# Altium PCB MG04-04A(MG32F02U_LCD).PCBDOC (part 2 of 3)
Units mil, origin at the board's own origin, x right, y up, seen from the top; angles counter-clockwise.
Board outline 5905.51 x 3543.31 mil, 2 copper layers (Top Layer, Bottom Layer); 293 components, 227 nets, 959 pads, 508 vias.
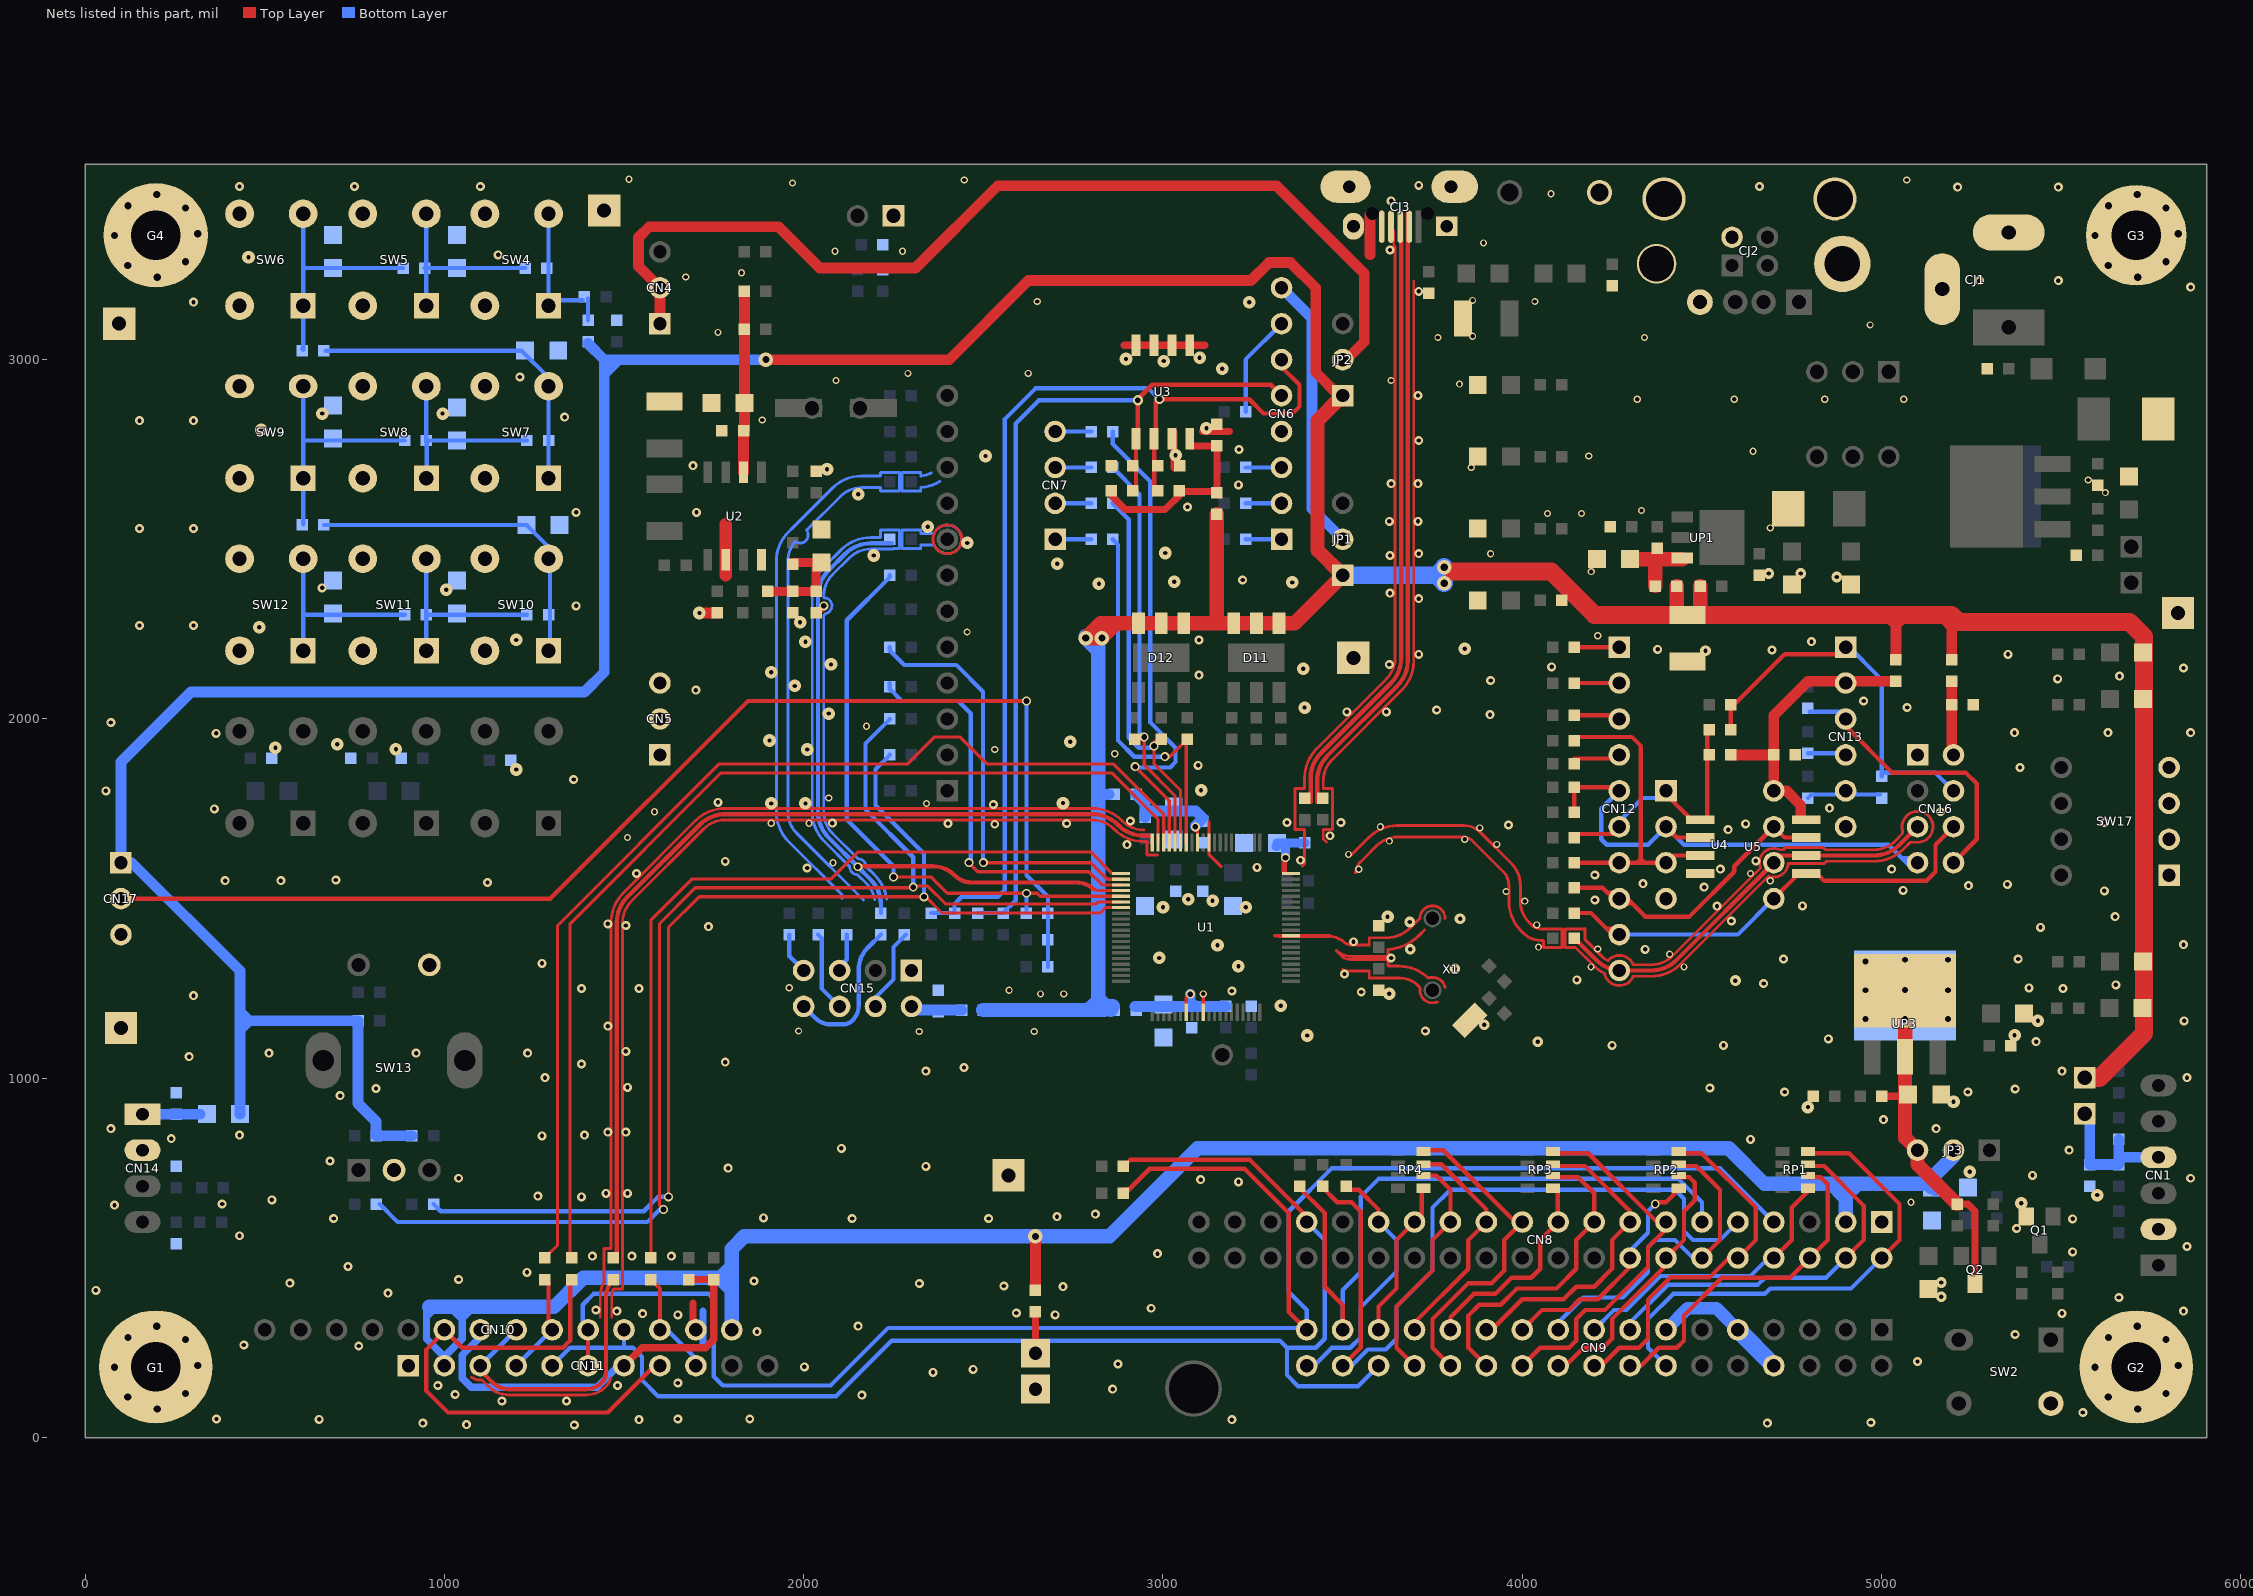
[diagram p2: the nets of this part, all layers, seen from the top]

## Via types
v1: diameter 25, hole 12, Top Layer to Bottom Layer, tented both sides, 253 vias
v2: diameter 25, hole 16, Top Layer to Bottom Layer, tented both sides, 83 vias
v3: diameter 20, hole 12, Top Layer to Bottom Layer, tented both sides, 77 vias
v4: diameter 35, hole 12, Top Layer to Bottom Layer, tented both sides, 64 vias
v5: diameter 40, hole 20, Top Layer to Bottom Layer, tented both sides, 16 vias
v6: diameter 30, hole 12, Top Layer to Bottom Layer, tented both sides, 13 vias
v7: diameter 28, hole 16, Top Layer to Bottom Layer, tented both sides, 2 vias

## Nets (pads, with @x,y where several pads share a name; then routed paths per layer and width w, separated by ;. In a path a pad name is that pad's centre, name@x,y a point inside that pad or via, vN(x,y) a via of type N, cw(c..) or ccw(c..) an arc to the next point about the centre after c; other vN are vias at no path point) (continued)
+LCD_LDO: C10.1 FB10.1 JP3.3 Q2.3 R9.1 UP3.2 UP3.4 | length 1102.5
  Top Layer w20: R9.1@5010,950 C10.1@5065,950 ; FB10.1@5210,650 5240,650 5260,630 Q2.3@5260,427.26
  Top Layer w32: UP3.4@5065,1175 UP3.4@5065,1176 ; UP3.4@5066,1150 5066,1165 UP3.4@5066,1175
  Top Layer w40: 5065,910 5065,835 ; UP3.2@5065,1082 UP3.2@5065,1060 C10.1@5065,950 ; UP3.4@5065,1266 5066,1265 5066,1165 UP3.2@5066,1082 ; C10.1@5074,950 C10.1@5065,950 ; FB10.1@5210,650 5100,760 JP3.3@5100,800 5065,835 ; 5065,835 C10.1@5065,950
  other v2: 4955,1165 5065,1165 5185,1165 4955,1245 5185,1245 5065,1246 4955,1325 5065,1330 5185,1330
+LCD_VCC: C36.1 CN8.2 CN10.1 CN11.2 JP3.2 R64.2 | length 5607.7
  Top Layer w30: R64.2@2645,410 v5(2645,560)
  Bottom Layer w20: 950,363 950,275 CN11.2@1000,225 ; 951,336.81 976,361.81 ; CN11.2@1000,200 CN11.2@1000,225 ; 1023,355 1048,330 ; 1050,350 1050,332 ; 1075,357 1050,332 ; 1761,436 1786,411 ; 1762,452 1787,477 ; CN11.2@1000,225 1050,275 1050,332
  Bottom Layer w30: 4860,700 4890,670 ; 4900,666 4940,706 ; C36.1@5150,686 C36.1@5150,706
  Bottom Layer w40: 958,363.69 1305,363.69 1386.31,445 1800,445 ; CN10.1@1800,300 1800,445 ; CN8.2@4900,600 4900,666 4900,706 ; C36.1@5140,696 C36.1@5140,706 ; JP3.2@5200,800 5200,783 5140,723 C36.1@5140,706 ; 1800,445 1800,525 1835,560 v5(2645,560) 2851,560 3096,805 4575,805 4674,706 4900,706 ; 4900,706 4940,706 C36.1@5140,706
+V33_MG: C21.1 R17.1 U1.60 | length 144.8
  Top Layer w15: 3338,1575 v2@3338,1613.77
  Bottom Layer w25: C21.1@3315,1645 C21.1@3317.81,1645 ; C21.1@3317.81,1655 R17.1@3395,1655 ; v2(3341,1614) C21.1@3341,1640
+VDD: CN17.1 D7.1 D8.1 D9.1 D10.1 D11.1 D11.3 D11.5 D12.1 D12.3 D12.5 D13.1 FB2.2 FB3.2 FB4.1 FB5.2 FB6.2 FB8.1 FB11.2 FB12.2 FB13.2 JP1.1 JP2.1 R3.1 R105.1 R115.1 R116.2 R118.2 TC3.1 | length 15368.9
  Top Layer w20: 5013,2282 5040,2255 5067,2282 ; 5168,2277 5195,2250 5215,2270 5222,2277
  Top Layer w30: v5(1895,3000) 2405,3000 2625,3220 3245,3220 3295,3270 3355,3270 3425,3200 3425,2965 3495,2895 JP2.1@3500,2890 ; JP1.1@3500,2400 JP1.1@3510,2400 ; FB11.2@5040,2165 5040,2255 5040,2270 ; FB13.2@5195,2180 5195,2250 5195,2290
  Top Layer w40: v5(2830,2225) v5@2828.54,2225 ; 3150,2268.46 FB8.1@3150,2570 ; JP2.1@3495,2895 3430,2830 3430,2470 JP1.1@3500,2400 3366.46,2266.46 D11.1@3322.99,2266.46 D11.3@3260,2266.46 D11.5@3197.01,2266.46 D12.1@3057.99,2266.46 D12.3@2995,2266.46 D12.5@2932.01,2266.46 2870,2266.46 ; JP2.1@3500,2890 JP2.1@3500,2900 ; TC3.1@4430,2300 FB3.2@4430,2370 ; TC3.1@4495,2300 FB2.2@4495,2370 ; v5@2828.54,2225 2870,2266.46 ; v5@2828.54,2225 v5(2785,2225) 2826.46,2266.46 2870,2266.46
  Top Layer w50: 3810,2410 4080.59,2410 4200.59,2290 TC3.1@4460,2290 ; TC3.1@4506,2290 5195,2290 5215,2270 5690,2270 5730,2230 5730,1125 ; FB6.2@5565,1001 5606,1001 5730,1125 ; D9.1@5730,2055 5730,1125
  Bottom Layer w12: 2778,1195 2808,1225 ; 2830,1232 FB5.2@2860,1202
  Bottom Layer w30: D13.1@431,900 431,1135 ; R118.2@910,840 R116.2@810,840 810,880 760,930 R115.1@760,1160 456,1160 ; R105.1@1400,3045 1445,3000 ; v5@1900,3000 v5(1895,3000) 1485,3000 ; 2820,1790 FB4.1@2850,1790 ; JP1.1@3490,2405 3505,2405 JP1.1@3510,2400 ; 431,1135 431,1160 ; 431,1135 456,1160 ; 431,1160 456,1160 ; 431,1160 431,1185 ; 431,1185 431,1299 130,1600 CN17.1@100,1600 100,1880 295,2075 1390,2075 1445,2130 1445,2960 ; 431,1185 456,1160 ; 1445,2960 1485,3000 ; 1445,2960 1445,3000 ; 1445,3000 1485,3000
  Bottom Layer w40: FB12.2@2500,1190 2837,1190 ; v5(2785,2225) 2820,2190 ; v5@2785,2230 v5@2830,2230 ; v5@2820,2220.86 2820,2190 ; FB5.2@2855,1190 FB5.2@2855,1200 ; FB5.2@2860,1200 FB5.2@2855,1200 ; v5@3787.7,2377.7 v5@3787.7,2422.3 ; 2820,2190 2820,1790 2820,1200 FB5.2@2855,1200
  Bottom Layer w50: JP1.1@3510,2400 3760.4,2400 ; 3780,2400 3760.4,2400 ; v5(3782.7,2377.7) 3760.4,2400 ; v5(3782.7,2422.3) 3760.4,2400
+VDD_AMP: C26.1 C27.1 FB7.2 FB14.2 U2.6 | length 498.3
  Top Layer w30: U2.6@1832.71,2686.65 C27.1@1832.71,2802.71 C27.1@1832.71,2805 ; C27.1@1835,2805 FB7.2@1835,3085 FB14.2@1835,3185
+VDD_BLE: C54.1 CN15.2 FB12.1 | length 140
  Bottom Layer w30: CN15.2@2300,1190 FB12.1@2440,1190
+VDD_BLE2: C55.1 CN16.2 FB13.1 | length 200
  Top Layer w30: CN16.2@5195,1905 C55.1@5195,2040 FB13.1@5195,2100 ; CN16.2@5200,1900 CN16.2@5200,1905
+VDD_EP: C32.1 FB8.2 R44.1 R45.1 U3.8 | length 543.2
  Top Layer w20: R44.1@2858.13,2626.75 2858.13,2619.87 2895,2583 3006,2583 3050,2627 3050,2633 FB8.2@3150,2633 ; U3.8@3075,2760 C32.1@3150,2760 FB8.2@3150,2633 ; FB8.2@3150,2630 FB8.2@3150,2633
+VDD_FS: C38.1 CN13.2 FB11.1 R75.1 U4.8 U5.8 | length 810.9
  Top Layer w30: R75.1@4580,1900 C38.1@4690,1900 ; U5.8@4775,1725 4775,1760 4735,1800 U4.8@4700,1800 C38.1@4700,1900 4700,2010 4795,2105 FB11.1@5025,2105
+VDD_I2C: CN6.8 JP1.2 | length 825.5
  Bottom Layer w30: CN6.8@3329.92,3200 CN6.8@3329.96,3199.96 ; CN6.8@3330,3200 3415,3115 3415,2815 ; 3415,2780 3415,2815 ; JP1.2@3490,2500 JP1.2@3500,2500 ; JP1.2@3510,2500 JP1.2@3500,2500 ; 3415,2815 3415,2585 JP1.2@3500,2500
+VDD_LDO: C6.1 FB3.1 R6.1 UP1.3 | length 195
  Top Layer w40: C6.1@4320,2444 UP1.3@4445,2444 ; FB3.1@4370,2370 4370,2440
+VDD_MG1: C15.1 C16.1 FB4.2 R11.2 U1.72 | length 307.5
  Top Layer w9: U1.72@3096.38,1656.22 v2@3096.38,1700
  Bottom Layer w30: FB4.2@2925,1790 2950,1765 R11.2@2950,1726 ; 2961,1744 3091,1744 3111.5,1723.5 v2@3090,1702
  other v2: 3090,1700
+VDD_MG2: C23.1 C24.1 FB5.1 R15.2 U1.27 | length 341.9
  Top Layer w10: U1.27@3064.88,1183.78 3064.88,1222.88 v2(3076,1234)
  Bottom Layer w30: FB5.1@2922,1200 C24.1@3076,1200 ; v2(3076,1234) C24.1@3076,1200 ; R15.2@3175.12,1200 C24.1@3079.88,1200 C24.1@3076,1200
+VDD_MX: CN4.1 CN4.2 JP2.2 | length 2801.8
  Top Layer w30: CN4.1@1600,3100 CN4.2@1600,3200 1540,3260 1540,3340 1570,3370 1930,3370 2045,3255 2311,3255 2540.25,3484.25 3315.75,3484.25 3560,3240 3560,3050 JP2.2@3510,3000
+VDD_SWD: C25.1 CN1.4 FB6.1 R22.2 R23.2 | length 396.9
  Bottom Layer w30: FB6.1@5579.37,901 C25.1@5579.37,760 R22.2@5659.37,760 5660,760.63 R23.2@5660,830 ; 5665,780 CN1.4@5770.63,780
+VDD_UART0: C39.1 CN14.1 D13.2 | length 160
  Bottom Layer w30: CN14.1@160,900 C39.1@254.49,900 D13.2@320,900
ARGB_IO: CN17.2 R131.1 R132.1 R133.1 | length 3512.7
  Top Layer w12: CN17.2@100,1500 1295,1500 1845,2050 v2(2620,2050)
  Bottom Layer w12: v2(2620,2050) 2620,1565 2680,1505 R131.1@2680,1460 R132.1@2680,1385 R133.1@2680,1310
AU_OUT: C28.2 C31.1 R27.2 R28.1 R30.2 | length 311.2
  Top Layer w25: C28.2@1900,2355 R28.1@1970,2355 R30.2@2035,2355 C31.1@2035,2420 ; R27.2@1970,2435 C31.1@2050,2435 C31.1@2035,2420 ; C31.1@2035,2430 C31.1@2035,2420
BL_CTL2: CN10.8 CN11.7 R66.2 R69.2 | length 1198.9
  Top Layer w20: CN10.8@1100,280 CN10.8@1100,300 ; CN11.7@1500,200 1550,250 1727.72,250 ; R66.2@1680,440 R69.2@1750,440 1750,273.19 1727.72,250.91
  Bottom Layer w20: CN10.8@1100,300 1100,280 1050,230 1050,165 1075,140 1425,140 1500,215 CN11.7@1500,200
BL_IRQ: CN15.8 R130.1 | length 422.7
  Bottom Layer w12: CN15.8@2000,1200 2031.68,1168.32 ; R130.1@2215,1400 2178.56,1363.56 ccw(c2240.27,1301.85) 2153,1301.85 2153,1201.59 cw(c2096.05,1201.59) 2136.32,1161.32 cw(c2108.99,1188.65) 2108.99,1150 2075.92,1150 cw(c2075.92,1212.58) 2031.83,1168.17 ; 2031.68,1168.32 ccw(c2075.92,1212.58) 2031.83,1168.17 ; 2031.68,1168.32 2031.83,1168.17
BL_MISO: CN15.7 R127.1 | length 116.6
  Bottom Layer w12: R127.1@1960,1400 1960,1340 CN15.7@2000,1300
BL_MOSI: CN15.6 R129.1 | length 224.9
  Bottom Layer w12: R129.1@2040,1400 2050,1390 2050,1250 CN15.6@2100,1200
BL_NSS: CN15.4 R126.1 | length 235.2
  Bottom Layer w12: CN15.4@2200,1200 2200,1225 2250,1275 2250,1365 R126.1@2285,1400
BL_SCK: CN15.5 R128.1 | length 123.3
  Bottom Layer w12: CN15.5@2085,1300 CN15.5@2100,1300 2100,1310 2120,1330 R128.1@2120,1400
FLASH_AUX: CN13.3 CN16.8 R96.2 | length 818.3
  Top Layer w12: CN13.3@4899.92,2000 4899.92,1980.08 5030,1850 5235,1850 5265,1820 5265,1665 CN16.8@5200,1600
  Bottom Layer w12: R96.2@4800,2020 4900,2020 CN13.3@4899.92,2000 CN13.3@4899.96,1999.96
FLASH_CEN: CN12.6 R75.2 R83.2 R84.2 U4.1 U5.1 | length 727.8
  Top Layer w12: R83.2@4145,1680 4250.08,1680 CN12.6@4270.08,1700 ; U4.1@4400,1800 4400,1790 4470,1720 U5.1@4495,1720 U5.1@4499.72,1720 ; U5.1@4515,1715 4515,1955 R84.2@4530,1970
  Bottom Layer w12: CN12.6@4245,1700 CN12.6@4257.5,1712.5 ; CN12.6@4250.08,1700 CN12.6@4270,1700 4270,1715 4335,1780 U4.1@4385,1780
FLASH_CEN2: CN13.1 CN16.4 R84.1 R85.2 R99.1 | length 1078.3
  Top Layer w12: R84.1@4580,1970 4580,2039.59 R85.2@4580.21,2039.79 ; R85.2@4580,2040 4590,2040 4730,2180 4879.92,2180 CN13.1@4899.92,2200
  Bottom Layer w12: CN13.1@4899.92,2210.08 5000,2110 R99.1@5000,1840 ; R99.1@5010,1850 5150,1850 CN16.4@5200,1800
FLASH_D0: CN12.9 CN16.6 R91.2 U4.5 U5.5 | length 1249.6
  Top Layer w12: R91.2@4145,1460 4191,1460 CN12.9@4250.96,1400.04 ; 4237.92,1416 CN12.9@4257,1416 ; U4.5@4700,1500 U5.5@4770,1570 ; U5.5@4785,1570 U5.5@4790.28,1570 4820,1570 4840,1550 5125,1550 5150,1575 5150,1650 CN16.6@5200,1700
  Bottom Layer w12: CN12.9@4270.08,1400 4600,1400 U4.5@4700,1500
FLASH_D1: CN12.5 CN16.7 R86.2 R87.2 U4.2 U5.2 | length 1629.2
  Top Layer w12: 4145,1770 R87.2@4145,1740 R86.2@4145,1810 CN12.5@4260.08,1810 ; CN12.5@4250.08,1800 CN12.5@4260.08,1790 ; U4.2@4400,1700 4430,1670 U5.2@4495,1670 U5.2@4499.72,1670
  Bottom Layer w12: CN12.5@4270,1800 4220,1750 4220,1665 4235,1650 4350,1650 U4.2@4400,1700 4450,1650 4920,1650 ; 4758.82,1650 4920,1650 ; 5059,1613 CN16.7@5090,1613 ; CN16.7@5085,1584 5019,1650 4920,1650
FLASH_D2: CN12.7 R88.2 R89.2 U4.3 U5.3 | length 933
  Top Layer w12: R89.2@4145,1600 CN12.7@4270,1600 ; R88.2@4145,1950 4305,1950 4330,1925 4330,1611 ; CN12.7@4250.08,1600 CN12.7@4270,1600 ; U5.3@4499.72,1620 U5.3@4495,1620 4420,1620 U4.3@4400,1600 4340,1600 ; CN12.7@4270,1600 4319,1600 ; 4319,1600 4330,1600 ; 4319,1600 4330,1611 ; 4330,1600 4340,1600 ; 4330,1600 4330,1610 ; 4330,1610 4330,1611 ; 4330,1610 4340,1600
FLASH_D3: CN12.8 R90.2 U4.7 U5.7 | length 822
  Top Layer w12: R90.2@4145,1530 4224,1530 CN12.8@4253.96,1500.04 ; 4238.92,1517 CN12.8@4255,1517 ; CN12.8@4283,1487 4304.92,1487 ; CN12.8@4291.96,1500.04 4342,1450 4465,1450 4590,1575 4590,1590 U4.7@4700,1700 4730,1670 U5.7@4790.28,1670 U5.7@4795,1670
  Bottom Layer w12: CN12.8@4250.08,1500 CN12.8@4260.08,1510
FLASH_D4: CN12.4 R82.2 | length 130
  Top Layer w12: R82.2@4145,1890 CN12.4@4275,1890
FLASH_D5: CN12.1 R78.2 | length 105.1
  Top Layer w12: R78.2@4145,2200 CN12.1@4250.08,2200
FLASH_D6: CN12.2 R80.2 | length 105.1
  Top Layer w12: R80.2@4145,2100 CN12.2@4250.08,2100
FLASH_D7: CN12.3 R81.2 | length 125
  Top Layer w12: R81.2@4145,2010 CN12.3@4270,2010
FLASH_DQS: CN13.4 R97.2 | length 99.9
  Bottom Layer w12: R97.2@4795,1905 CN13.4@4894.92,1905
FLASH_RSTN: CN13.5 R98.2 R99.2 | length 204.1
  Bottom Layer w12: R98.2@4795,1780 4805,1790 R99.2@4995,1790
FLASH_SCK: CN12.10 CN16.5 R94.2 U4.6 U5.6 | length 1168.5
  Top Layer w12: R94.2@4145,1390 4205.71,1329.29 ccw(c4276.42,1400) CN12.10@4276.42,1300 ; CN12.10@4251.42,1300 CN12.10@4270,1300 CN12.10@4276.42,1300 ; U4.6@4700,1600 4429.29,1329.29 cw(c4358.58,1400) 4358.58,1300 CN12.10@4276.42,1300 ; U4.6@4705,1620 U5.6@4790.28,1620 4978.58,1620 ccw(c4978.58,1720) 5049.29,1649.29 CN16.5@5100,1700 ; U5.6@4827.28,1620.03 4838.99,1620.03
GND: _DC_GND1.1 C1.2 C2.2 C3.2 C4.2 C5.2 C6.2 C7.2 C8.2 C9.2 C10.2 C11.2 C12.2 C13.2 C14.2 C15.2 C16.2 C17.2 C18.2 C19.2 C20.2 C21.2 C22.2 C23.2 C24.2 C25.2 C26.2 C27.2 C30.2 C31.2 C32.2 C33.2 C34.2 C35.2 C36.2 C37.2 C38.2 C39.2 C40.2 C41.2 C42.2 C43.2 C44.2 C45.2 C46.2 C47.2 C48.2 C49.2 C50.2 C51.2 C54.2 C55.2 CJ1.2 CJ1.3 CJ2.4 CJ2.5 CJ2.6 CJ2.10 CJ2.11 CJ2.12 CJ3.4 CJ3.5 CJ3.6 CJ3.7 CJ3.8 CJ3.9 CJ3.11 CN1.2 CN2.1 CN5.1 CN5.2 CN5.3 CN6.4 CN8.1 CN9.8 CN9.9 CN9.13 CN10.2 CN11.1 CN13.6 CN14.2 CN15.1 CN16.1 CN17.3 D1.2 D2.2 D3.2 D4.2 G1.1 G1.2 G1.3 G1.4 G1.5 G1.6 G1.7 G1.8 G1.9 G2.1 G2.2 G2.3 G2.4 G2.5 G2.6 G2.7 G2.8 G2.9 G3.1 G3.2 G3.3 G3.4 G3.5 G3.6 G3.7 G3.8 G3.9 G4.1 G4.2 G4.3 G4.4 G4.5 G4.6 G4.7 G4.8 G4.9 JP4.2 Q1.2 R7.2 R8.2 R10.2 R28.2 R29.2 R31.2 R32.2 R119.1 R121.1 R122.1 SW2.2 SW4.2 SW4.4 SW5.2 SW5.4 SW6.2 SW6.4 SW7.2 SW7.4 SW8.2 SW8.4 SW9.2 SW9.4 SW10.2 SW10.4 SW11.2 SW11.4 SW12.2 SW12.4 SW13.2 SW13.4 SW17.1 SW17.2 SW17.3 SW17.4 TC1.2 TC2.2 TC3.2 TC5.2 TP1.1 TP2.1 TP3.1 TP4.1 TP5.1 TP6.1 U1.30 U1.49 U1.70 U2.2 U2.4 U3.1 U3.2 U3.3 U3.4 U3.7 U4.4 U5.4 X1.3 Z1.1 | length 23636.5
  Top Layer w8: 1075.83,168.13 ccw(c1100,200) 1100,160 1105.01,160 1122.65,142.36 ccw(c1179.12,198.93) 1179.12,119 1395.25,119 ccw(c1395.25,194.75) 1448.78,141.15 ; 1434,335 1434,391.72 ; 1448.81,141.19 ccw(c1407.32,182.68) 1463.42,165.48 ; 1466,335 1466,391.72 ; 1497.98,1515.6 ccw(c1580,1433.58) 1464,1433.58 1464,526 1444,526 1444,431.54 ; 1497.99,1515.62 1699.38,1717.01 ; 1520.6,1492.98 ccw(c1580,1433.58) 1496,1433.58 1496,414 1470.99,414 ; 1520.62,1492.99 1722.01,1694.38 ; 1699.4,1717.02 cw(c1781.42,1635) 1781.42,1751 2803.58,1751 cw(c2803.58,1635) 2885.6,1717.02 ; 1722.02,1694.4 cw(c1781.42,1635) 1781.42,1719 2803.58,1719 cw(c2803.58,1635) 2862.98,1694.4 ; 2864.4,1692.98 ccw(c2946.42,1775) 2946.42,1659 2955.89,1659 2955.89,1621.22 2984.89,1621.22 ; 2887.02,1715.6 ccw(c2946.42,1775) 2946.42,1691 ; 3321.22,1395.13 3464.34,1395.13 cw(c3464.34,1344.34) 3494.17,1385.45 cw(c3490,1370) 3501.31,1381.31 ccw(c3526.21,1406.21) 3526.21,1371 3574,1371 3574,1391 3621,1391 ccw(c3621,1487) 3687.34,1417.61 ; 3388,1591.11 3394,1597.11 3394,1692.24 3367.41,1692.24 3367.41,1806.24 3394,1806.24 3394,1834 ; 3394,1835.03 cw(c3511,1835.03) 3428.27,1917.77 ; 3428.29,1917.79 3621.67,2111.17 ; 3454.8,1657.2 3446,1666 3446,1692.24 3471.41,1692.24 3471.41,1806.24 3446,1806.24 3446,1828 cw(c3527.98,1828) 3469.98,1885.93 ; 3470.03,1885.99 3664.62,2080.58 ; 3497.18,1340.45 3482.29,1355.34 ccw(c3526.21,1406.21) 3526.21,1339 3626,1339 3626,1359.1 ccw(c3621,1487) 3713.22,1398.23 3727.49,1412.51 ; 3497.22,1340.41 ccw(c3520,1363.28) 3520,1331 3626,1331 3626,1312 3657.66,1312 cw(c3657.66,1197.74) 3738.45,1278.53 cw(c3750.78,1245.78) 3785.18,1252.21 ; 3499.42,1302.38 ccw(c3520,1363.28) 3520,1299 3574,1299 3574,1279 3660,1279 cw(c3660,1209.64) 3709.01,1258.72 ; v3@3515,1622 3524.37,1622 3533.67,1631.3 ; 3533.7,1631.33 3571.93,1669.56 ; 3536.2,1572.2 cw(c3575.74,1572.2) 3547.75,1600.12 ; 3547.8,1600.17 3556.3,1608.67 ; 3556.33,1608.7 3594.56,1646.93 ; 3571.95,1669.58 cw(c3653.97,1587.55) 3650.19,1703.49 ; 3594.58,1646.95 cw(c3653.97,1587.55) 3653.97,1671.55 3837.45,1671.55 cw(c3837.45,1639.27) 3860.28,1662.1 ; 3621.69,2111.19 ccw(c3563,2169.88) 3646,2169.88 3646,3315 ; CJ3.4@3632.06,3367.65 CJ3.4@3641.13,3358.57 ; CJ3.4@3641.13,3338.5 CJ3.4@3641.13,3358.57 ; v1@3642.13,3300 3642.13,3357.57 CJ3.4@3641.13,3358.57 ; 3650.19,1703.55 3837.45,1703.55 cw(c3837.45,1639.27) 3882.9,1684.72 3972.43,1595.2 ; 3664.69,2080.65 ccw(c3584.1,2161.14) 3698,2161.14 3698,3217.78 ; v6@3690.25,1420.52 cw(c3621,1487) 3687.37,1417.64 3714.76,1445.03 ; 3709.06,1258.67 3715.71,1252.02 ccw(c3750,1245) 3763.54,1212.72 ; 3715,1445.27 cw(c3750,1445) 3785,1445 ; 3860.29,1662.08 3949.38,1573 cw(c3906.31,1536.54) 3962.73,1537.32 ; 3962.73,1536.54 3962.73,1492.69 ccw(c4078.73,1492.69) 3996.7,1410.67 4003.68,1403.69 ; 3973.24,1594.32 cw(c3906.31,1536.54) 3994.73,1537.76 ; 3994.73,1536.54 3994.73,1492.69 ccw(c4078.73,1492.69) 4019.33,1433.3 ; 4003.7,1403.68 ccw(c4051.21,1451.21) 4051.21,1384 4059,1384 ; 4019.35,1433.28 4026.31,1426.32 ; 4026.35,1426.27 ccw(c4051.21,1451.21) 4051.21,1416 4111,1416 4111,1364 4059,1364 4059,1382.32 ; 4171,1416 4119,1416 4119,1364 4148.37,1364 4198.64,1313.74 ccw(c4283.49,1398.59) 4227.83,1292.28 ; 4174,1416.37 4174,1387 4222.76,1338.24 ; 4219.58,1340.88 ccw(c4267.73,1389.03) 4237.21,1328.15 ; 4228.76,1292.45 ccw(c4270.08,1300) 4308.57,1283.2 ; 4238.18,1327.32 cw(c4270.08,1300) 4308.57,1316.8 ; 4308.57,1284 4358.58,1284 ccw(c4358.58,1400) 4440.6,1317.98 ; 4308.57,1316 4358.58,1316 ccw(c4358.58,1400) v3@4417.98,1340.6 ; v3@4417.99,1340.62 4662.76,1585.39 cw(c4700,1600) 4717.44,1636 4726.28,1636 4733.28,1643 ; 4440.62,1317.99 4685.39,1562.76 ccw(c4700,1600) 4739.95,1598.02 ; 4730.28,1642 4837.46,1642 4843.46,1636 4978.58,1636 ccw(c4978.58,1720) 5037.98,1660.6 ; 4740.28,1598 4840.28,1598 4846.28,1604 4978.58,1604 ccw(c4978.58,1720) 5060.6,1637.98 ; 5037.99,1660.62 5058.28,1680.91 5058.28,1689.57 cw(c5100,1700) 5101.66,1657.03 5079.66,1657.03 5060.62,1637.99 ; 1434,391.72 cw(c1518.28,391.72) 1444,431.54 ; 1434,391.72 cw(c1518.28,391.72) 1444,431.54 ; 1466,391.72 cw(c1518.28,391.72) 1470.99,414 ; 1466,391.72 cw(c1518.28,391.72) 1470.99,414 ; 2440,2500 ccw(c2400,2500) 2440,2500
  Top Layer w9: 3127.87,1713.39 U1.70@3127.87,1656.22 3127.87,1623.13 3161.91,1589.09 ; U1.49@3356.22,1396.38 3464.34,1396.38
  Top Layer w10: U1.30@3112.13,1183.78 v3@3112.13,1225.69 ; 3311.47,1396.38 U1.49@3356.22,1396.38
  Top Layer w20: CN10.2@1691.81,305 1691.81,375 ; 2891.81,3040 3116.81,3040 ; C34.2@3031,2699 U3.7@3031,2799 ; v4@3110,2800 3185,2800
  Top Layer w30: v4(1710,2295) R29.2@1760,2295 ; 3576,3291.81 CJ3.11@3576,3401.81
  Top Layer w35: 1782.71,2400.65 U2.2@1782.71,2442.65 1782.71,2542.29
  Bottom Layer w8: 1957.98,1659.4 cw(c2040,1741.42) 1924,1741.42 1924,2438.58 cw(c2040,2438.58) 1957.98,2520.6 ; 1957.99,1659.38 2106.62,1510.76 2106.62,1500.86 ; 1957.99,2520.62 1969.67,2532.3 ; 1969.7,2532.33 2079.57,2642.2 cw(c2161.61,2560.19) 2161.61,2676.19 2214,2676.19 2214,2686 2266,2686 2266,2634 2214,2634 2214,2644.19 2161.61,2644.19 ccw(c2161.61,2560.19) 2102.21,2619.59 2008.05,2525.43 cw(c1990,2512) 2012.5,2512 cw(c1990,2512) 1976.73,2493.83 ccw(c2040,2438.58) 1956,2438.58 1956,1741.42 ccw(c2040,1741.42) 1980.6,1682.02 2166.31,1496.31 ; 2024,1740.35 ccw(c2140,1740.84) 2057.98,1658.82 ; 2024,1740.42 2024,2342.58 cw(c2140,2342.58) 2057.98,2424.6 ; 2056,1740.42 2056,2287.8 2061.34,2293.14 ccw(c2056,2315) 2056,2337.5 ; 2056,1740.45 ccw(c2140,1740.84) 2080.6,1681.45 ; 2056,2342.58 cw(c2140,2342.58) 2080.6,2401.98 ; 2057.99,1658.8 2128.21,1588.58 ccw(c2150.71,1588.71) 2150.04,1566.22 ; 2057.99,2424.62 2104.38,2471.01 ; 2080.62,1681.43 2150.41,1611.64 ; 2080.62,2401.99 2127.01,2448.38 ; 2104.4,2471.02 cw(c2186.42,2389) 2186.42,2505 2214,2505 2214,2526 2266,2526 2266,2474 2250.57,2474 cw(c2245,2489) 2245,2473 2186.42,2473 ccw(c2186.42,2389) 2127.03,2448.4 ; 2150.58,1566.21 2174.59,1542.21 cw(c2115.19,1482.81) 2197.99,1496.93 ; 2155.15,1610.77 cw(c2150.71,1588.71) 2173.21,1588.84 ; 2174.21,1588.84 2198.22,1564.83 cw(c2116.19,1482.81) 2231.15,1498.34 ; 2355.27,2684.44 cw(c2318.58,2760) 2326,2676.33 2326,2686 2274,2686 2274,2634 2326,2634 2326,2644.24 ccw(c2318.58,2760) 2379.29,2661.16 ; 2274,2474 2326,2474 2326,2484 2363.34,2484 ccw(c2400,2500) 2440,2500 ccw(c2400,2500) 2363.34,2516 2326,2516 2326,2526 2274,2526 2274,2474
  Bottom Layer w20: 1720,258.37 1720,352
  Bottom Layer w32: CN9.9@4600,300 4600,306.81 CN9.9@4606.81,300
  Bottom Layer w35: CN9.13@4400,300 4460,360 4540,360 CN9.9@4600,300
  Bottom Layer w50: CN9.9@4600,300 CN9.8@4700,200
  other v1: 1361.81,35 1061.81,36 940,40 4681.81,40 4970,41.81 1541.81,50 3191.81,50 651.81,51 366,51.81 1650,51.81 1850,51.81 5560,70 1160,101.81 1340,101.81 2161.81,118 1030,120 2860,135 981.81,145 1481.81,145 1650,151.81 2360,181.81 2471.81,190 2001.81,197 2875,205 5100,211.81 761.81,255 441.81,258 5371.81,287 1870,295 2151.81,310 1650,341.81 2700,341.81 1551.81,345 5501.81,346 2591.81,347 1480,351.81 5840,351.81 1421.81,355 2967.32,360 5660,390 843,401.81 30,410 2721.81,420 2557,421.81 2321.81,429 570,430 1861.81,436 1040,440 1230,460 731.81,476 1411.81,505 1521.81,505 1631.81,505 2985,511.81 5531.81,517 5850,531.81 430,561.81 5376,581.81 5531.81,609 691.81,610 2135,610 2515,610 1888,611.81 2705,615 2811.81,622 81.81,647 381.81,650 520,661.81 1381.81,670 1260,671.81 1450,680 1510,680 3210,712 3105,718 1040,721.81 5860,721.81 5420,730 1790,750 2340,755 681.81,770 5521.81,800 2105,805 4635,830 240,831.81 1271.81,840 430,841.81 1390,841.81 1455,850 1505,850 71.81,860 5151.81,860 5005,885 710,951.81 4730,961.81 5240,961.81 5371.81,970 810,971.81 4521.81,973 1510,975 1280,1001.81 5850,1001.81 2340,1020 5501.81,1020 2446,1030 1381.81,1040 1781.81,1045 290,1060 511.81,1070 921.81,1070 1231.81,1070 1505,1075 4250,1091.81 4560,1091.81 5430,1101.81 4851.81,1110 3730,1131.81 1455,1145 5841.81,1160 301.81,1230 3551.81,1240 3191.81,1243 1381.81,1250 1541.81,1250 5505,1250 5410,1251.81 5651.81,1260 4671.81,1264 4151.81,1274 3505,1290 1271.81,1320 4727,1331.81 5380,1331.81 3635,1335 4341.81,1359 5840,1371.81 3530,1380 5442,1420 1735,1421.81 1505,1425 1455,1430 4581.81,1438 5650,1450 4541.81,1479 4780,1480 4201.81,1496 5620,1521.81 5060,1523 4506,1531.81 5241.81,1536 5350,1540 4336,1541.81 1120,1545 390,1550 545,1550 698.19,1551.81 4201.81,1566 1535,1570 4551,1581.81 5028,1581.81 2009.78,1585.18 3261.81,1587 1781.81,1604 4650,1605 3382.86,1606.81 2900,1650 3465,1675 4573,1691.81 3961.81,1705 2531.81,1707 4621.81,1708 2401.81,1709 2731.81,1709 2080,1710 3345,1711.81 3495,1711.81 5620,1711.81 2909,1716 5164,1741.81 360,1750 4855,1751.81 2528,1761.81 1761.81,1768 58,1800 1360,1831.81 5385,1865 3098,1871 365,1960 5370,1961.81 5630,1961.81 5860,1961.81 71.81,1990 3910,2011.81 3511.81,2020 3621.81,2020 3761.81,2025 5071,2031.81 4949.92,2050 1700,2080 3911.81,2107 5490,2111.81 5661.81,2119 3100,2121.81 5840,2141.81 4081.81,2145 3630,2151.81 3711.81,2180 5351.81,2180 4695,2191.81 4376.81,2194 4805,2215 3100,2220 151.81,2260 301.81,2260 1366.81,2315 3711.81,2335 3631.81,2350 660,2365 3221.81,2387 3631.81,2455 3711.81,2460 151.81,2530 301.81,2530 3630,2550 3710,2550 1366.81,2575 1701.81,2575 3068,2590 3210,2651.81 3635,2655 3710,2655 1691.81,2705 3211.81,2750 3711.81,2775 151.81,2830 301.81,2830 1335,2840 3710,2900 1210,2951.81 301.81,3160 3711.81,3190 5860,3201.81 5271.81,3220 5491.81,3220 1150,3291.81 3631.81,3305 3635,3441.81 5211.81,3480 5491.81,3480 430,3481.81 750,3481.81 1100,3481.81 4660,3481.81 3711.81,3485
  other v3: 5081.81,655 2321.81,1130 2641.81,1130 1986,1131.81 2659,1235 2724,1235 3112,1235 2571.81,1245 1960,1251.81 4191.34,1310 4450,1310 4410,1345 4210,1360 4045,1365 4040,1427 4007,1493 3955,1520 4690,1550 4635,1570 3544.66,1581.81 2081.81,1600 3516.56,1623.19 3929,1651 3630,1660 3840,1665 1510,1670 3881.81,1697 3605,1700 1910,1710 2015,1710 1585,1741.81 2341.81,1765 2070,1780 2866,1903 2531.81,1915 2175,1980 4210,2231.81 2455,2241.81 4191.81,2410 3911.81,2460 4690,2531.81 4070,2571.81 4165,2571.81 4331.81,2580 5622.81,2630 5575,2665 3857.81,2700 4185,2731.81 4641.81,2745 1885,2831.81 4320,2890 4590,2890 4841.81,2890 5061.81,2890 3825,2931.81 2090,2941.81 3635,2941.81 2290,2961.81 2625,2961.81 3765,3061.81 4340,3061.81 3861.81,3065 1761.81,3076 4968,3096.81 2650,3161.81 4035,3161.81 3861.81,3165 1671.81,3230 1827,3241.81 2087,3301.81 2275,3301.81 3891.81,3325 4080,3461.81 1969,3491.81 2447,3500 5070,3500 1514,3501.81
  other v4: 5389,652 5600,675 5245,740 4795,920 5200,935 3401.81,1119 5370,1120 5435,1160 3328,1201.81 3630,1235 3210,1311.81 2990,1335 3151.81,1370 3625,1450 3000,1476 3230,1476 3138,1494 3070,1498 1910,1765 2005,1765 2721.81,1766 3106,1801.81 1200,1859.41 2010,1915 865.35,1916.01 530,1920 701.81,1930 2741.81,1937 1905,1940 2070,2015 3394,2031.81 1975,2092 1910,2130 3390,2140 2076,2151.81 3840,2195 2005,2215 1200,2220 485,2255 1990,2269 1005,2360 2821.81,2376 3360,2380 3031,2381.81 2706,2431.81 2195,2455 3006,2461.81 2455,2490 2345,2535 2151.81,2625 2065,2695 2506,2731.81 3035,2734 490,2805 3121,2809 660,2850 995,2850 3165,2975 3001.81,2996 2897,3001.81 3101.81,3005 3240,3160 455,3285
  other v6: 5166,391.81 5166,431.81 4043,1101.81 3894,1149 4593,1271.81 3812,1305 3688,1359 3687,1435 3827,1444 4510,2190 4875,2395 4686,2405 4775,2405
I2C_A0: CN6.1 R52.1 | length 99.9
  Bottom Layer w12: R52.1@3230,2500 CN6.1@3329.92,2500
I2C_A1: CN6.2 R53.1 | length 99.9
  Bottom Layer w12: R53.1@3230,2600 CN6.2@3329.92,2600
I2C_A2: CN6.3 R54.1 | length 99.9
  Bottom Layer w12: R54.1@3230,2700 CN6.3@3329.92,2700
I2C_AUX0: CN7.1 R55.1 | length 100
  Bottom Layer w12: CN7.1@2700,2500 R55.1@2800,2500
I2C_AUX1: CN7.2 R56.1 | length 100
  Bottom Layer w12: CN7.2@2700,2600 R56.1@2800,2600
I2C_AUX2: CN7.3 R57.1 | length 100
  Bottom Layer w12: CN7.3@2700,2700 R57.1@2800,2700
I2C_AUX3: CN7.4 R58.1 | length 125
  Bottom Layer w12: CN7.4@2675,2800 CN7.4@2700,2800 R58.1@2800,2800
I2C_SCL: C34.1 CN6.6 R45.2 R47.1 R49.1 U3.6 | length 2843.8
  Top Layer w12: R45.2@2976,2650 U3.6@2976,2780 ; U3.6@2980,2780 2980,2880 v7(2990,2890) 3239.92,2890 3279.92,2850 3359.92,2850 3379.92,2870 3379.92,2930 3330,2979.92 CN6.6@3330,3000 ; CN6.6@3329.92,3000 CN6.6@3329.96,2999.96
  Bottom Layer w12: R47.1@2355,1460 R49.1@2420,1460 2420,1485 2440,1505 2540,1505 2560,1525 2560,2834.85 2645.15,2920 2960,2920 v7(2990,2890)
I2C_SDA: C33.1 CN6.5 R44.2 R48.1 R50.1 U3.5 | length 2514.7
  Top Layer w12: R44.2@2920,2635 2925,2640 U3.5@2925,2780 ; U3.5@2930,2780 v7(2930,2887) 2930,2890 2970,2930 3299.92,2930 3329.92,2900 CN6.5@3329.92,2920.08
  Bottom Layer w12: R48.1@2485,1460 R50.1@2550,1460 ; R50.1@2555,1460 2590,1495 2590,2822.43 2654.57,2887 v7(2930,2887)
I2C_WP: CN6.7 R51.1 | length 286.4
  Bottom Layer w12: R51.1@3230,2855 3230,3000.08 CN6.7@3329.92,3100
KEY0: R105.2 R106.2 R107.1 SW4.1 SW4.3 | length 418.1
  Bottom Layer w12: SW4.1@1290,3150 1290,3160 SW4.1@1290,3165 ; SW4.3@1290,3406 SW4.1@1290,3165 ; R106.2@1385,3165 SW4.1@1290,3165 ; R105.2@1400,3110 R106.2@1400,3170
  Bottom Layer w30: SW4.1@1290,3160 SW4.1@1295,3155
KEY1: C43.1 R107.2 R108.1 SW5.1 SW5.3 | length 536
  Bottom Layer w12: R108.1@945,3255 R108.1@950,3255 ; SW5.1@950,3150 R108.1@950,3255 ; SW5.3@950,3406 R108.1@950,3255 ; R107.2@1225,3255 C43.1@1035,3255 R108.1@950,3255
KEY2: C44.1 R108.2 R109.1 SW6.1 SW6.3 | length 661.9
  Bottom Layer w12: R109.1@605,3030 R109.1@607,3032 ; R109.1@607,3027 R109.1@607,3032 ; SW6.3@607,3406 607,3250 ; R108.2@885,3255 C44.1@690,3255 612,3255 607,3250 ; R109.1@607,3032 SW6.1@607,3150 607,3250
KEY3: C45.1 R109.2 R110.1 SW7.1 SW7.3 | length 936.1
  Bottom Layer w12: R109.2@670,3025 1215,3025 SW7.3@1290,2950 ; SW7.1@1290,2670 R110.1@1290,2775 SW7.3@1290,2926 SW7.3@1290,2950 ; SW7.3@1290,2955 SW7.3@1290,2950
KEY4: C46.1 R110.2 R111.1 SW8.1 SW8.3 | length 536
  Bottom Layer w12: R111.1@950,2770 R111.1@950,2775 ; SW8.3@950,2926 R111.1@950,2775 ; SW8.1@951,2670 R111.1@951,2770 ; R110.2@1230,2775 C46.1@1035,2775 R111.1@950,2775
KEY5: C47.1 R111.2 R112.1 SW9.1 SW9.3 | length 667
  Bottom Layer w12: R112.1@607,2542 SW9.1@607,2670 607,2775 ; SW9.3@607,2926 607,2775 ; R111.2@890,2775 607,2775
KEY6: C48.1 R112.2 R113.1 SW10.1 SW10.3 | length 950.6
  Bottom Layer w12: R112.2@665,2540 C48.1@1229,2540 1290,2479 SW10.3@1290,2446 1294,2450 1294,2194 SW10.1@1290,2190
KEY7: C49.1 R113.2 R114.1 SW11.1 SW11.3 | length 536
  Bottom Layer w12: SW11.1@950,2190 R114.1@950,2290 ; SW11.3@950,2446 R114.1@950,2290 ; R113.2@1230,2290 R114.1@950,2290
KEY8: C50.1 R114.2 SW12.1 SW12.3 | length 539
  Bottom Layer w12: SW12.1@607,2190 607,2290 ; SW12.3@607,2446 607,2290 ; R114.2@890,2290 607,2290
LCD_CS: CN8.15 CN9.34 R61.2 | length 698.6
  Top Layer w12: R61.2@3525,690 3545,690 3600,635 CN8.15@3600,600
  Bottom Layer w12: CN9.34@3400,200 3420,200 3470,250 3521,250 3550,279 3550,362 3650,462 3650,550 CN8.15@3600,600
LCD_CS2: CN10.3 CN11.9 R72.2 | length 288.7
  Top Layer w12: R72.2@1575,440 1600,415 CN10.3@1600,300 ; CN10.3@1607.5,292.5 CN10.3@1607.5,300
  Bottom Layer w12: CN10.3@1617.5,302.5 CN11.9@1710,210
LCD_DB0: CN8.14 CN9.29 RP4.5 | length 430.2
  Top Layer w12: CN9.29@3600,300 3600,365 3650,415 3650,550 CN8.14@3700,600 ; CN8.14@3685,596.18 CN8.14@3685,600 ; CN8.14@3720,595 3720,680
LCD_DB1: CN8.13 CN9.28 RP4.6 | length 663.7
  Top Layer w12: CN9.28@3700,200 3650,250 3650,365 3750,465 3750,550 CN8.13@3800,600 3800,690 3760.75,729.25 RP4.6@3725.43,729.25
LCD_DB2: CN8.12 CN9.27 RP4.7 | length 644.5
  Top Layer w12: CN9.27@3700,300 3700,320 3850,470 3850,550 CN8.12@3900,600 3900,635 3774.25,760.75 RP4.7@3725.43,760.75
LCD_DB3: CN8.11 CN9.26 RP4.8 | length 903.4
  Top Layer w12: RP4.8@3725.43,791.18 3734.25,800 3780,800 3990,590 3950,550 3950,465 3915,430 3850,430 3750,330 3750,250 CN9.26@3800,200
LCD_DB4: CN8.10 CN9.25 RP3.5 | length 565.1
  Top Layer w12: CN9.25@3800,300 3800,335 3865,400 3925,400 3970,445 4025,445 4050,470 4050,550 CN8.10@4090,590 ; CN8.10@4098.82,601.18 RP3.5@4098.82,688.82
LCD_DB5: CN8.9 CN9.24 RP3.6 | length 867.6
  Top Layer w12: CN9.24@3900,200 3850,250 3850,340 3880,370 3940,370 3985,415 4095,415 4150,470 4150,550 CN8.9@4192.5,592.5 ; RP3.6@4085.43,724.25 4155.75,724.25 4200,680 CN8.9@4200,600
LCD_DB6: CN8.8 CN9.23 RP3.7 | length 867.8
  Top Layer w12: CN9.23@3900,300 3915,300 4000,385 4115,385 4150,420 4200,420 4250,470 4250,550 CN8.8@4300,600 4300,630 4174.25,755.75 RP3.7@4085.43,755.75
LCD_DB7: CN8.7 CN9.22 RP3.8 | length 1038.5
  Top Layer w12: CN9.22@4000,200 4050,250 4130,250 4150,270 4150,330 4175,355 4230,355 4350,475 4350,530 4400,580 CN8.7@4400,600 4375,600 4183.82,791.18 RP3.8@4085.43,791.18
LCD_DB8: CN8.28 CN9.21 RP2.5 | length 651
  Top Layer w12: CN9.21@4000,300 4055,355 4130,355 4160,385 4210,385 4300,475 CN8.28@4300,500 ; v2(4370,650) 4375,655 4400,655 RP2.5@4430,685
  Bottom Layer w12: CN8.28@4300,500 4300,520 4350,570 4350,630 v2(4370,650)
LCD_DB9: CN8.27 CN9.20 RP2.6 | length 776.8
  Top Layer w12: CN9.20@4100,200 4120,200 4170,250 4225,250 4250,275 4250,330 4407.5,487.5 4407.5,507.5 4450,550 4450,630 4480,660 4480,710 4465.75,724.25 RP2.6@4435.43,724.25
  Bottom Layer w12: CN8.27@4400,485 CN8.27@4400,500
LCD_DB10: CN8.26 CN9.19 RP2.7 | length 909.5
  Top Layer w12: RP2.7@4435.43,755.75 4484.25,755.75 4550,690 4550,550 CN8.26@4500,500
  Bottom Layer w12: CN9.19@4100,320 4170,390 4280,390 4350,460 4350,530 4370,550 4425,550 4475,500 CN8.26@4500,500
LCD_DB11: CN8.25 CN9.18 RP2.8 | length 1026
  Top Layer w12: CN9.18@4200,200 4220,200 4270,250 4325,250 4350,275 4350,384 4412,446 4521,446 4575,500 CN8.25@4600,500 4650,550 4650,640 4498.82,791.18 RP2.8@4435.43,791.18
LCD_DB12: CN8.24 CN9.17 RP1.5 | length 811.2
  Top Layer w12: CN8.24@4700,500 4750,550 4750,640 4795.43,685.43 RP1.5@4795.43,688.82
  Bottom Layer w12: CN9.17@4200,300 4255,355 4290,355 4385,450 4635,450 4685,500 CN8.24@4700,500
LCD_DB13: CN8.23 CN9.16 RP1.6 | length 953.5
  Top Layer w12: CN9.16@4300,200 4330,200 4380,250 4430,250 4450,270 4450,340 4555,445 4745,445 CN8.23@4800,500 4850,550 4850,705 4830.75,724.25 RP1.6@4795.43,724.25
LCD_DB14: CN8.22 CN9.15 RP1.7 | length 1061.3
  Top Layer w12: RP1.7@4795.43,755.75 4840.25,755.75 4950,646 4950,550 CN8.22@4900,500
  Bottom Layer w12: CN9.15@4300,300 4300,320 4405,425 4655,425 4675,445 4845,445 CN8.22@4900,500
LCD_DB15: CN8.21 CN9.14 RP1.8 | length 1354.9
  Top Layer w12: RP1.8@4795.43,791.18 4908.82,791.18 5050,650 5050,550 CN8.21@5000,500
  Bottom Layer w12: CN9.14@4400,200 4350,250 4350,330 4420,400 4675,400 4690,415 4915,415 CN8.21@5000,500
LCD_RD: CN8.6 CN9.31 R63.2 | length 1891.6
  Top Layer w12: R63.2@3377.5,697.5 3450,625 3450,420 3500,370 CN9.31@3500,300
  Bottom Layer w12: CN9.31@3500,300 3500,410 3550,460 3550,670 3600,720 4435,720 4500,655 CN8.6@4500,600
LCD_RS: CN8.4 CN9.33 CN10.5 CN11.6 R60.2 | length 5230.9
  Top Layer w12: CN11.6@1400,200 CN10.5@1400,300 ; R60.2@2890,690 R60.2@2900,690 ; R60.2@2895,675 2895,680 2963,748 3227,748 3350,625 3350,350 CN9.33@3400,300
  Bottom Layer w12: CN11.6@1400,200 CN11.6@1420,200 ; CN10.5@1400,310 1385,325 1385,370 1415,400 1735,400 1750,385 1750,170 1775,145 2075,145 2235,305 CN9.33@3400,305 ; CN9.33@3400,300 CN9.33@3400,305 ; CN9.33@3410,300 3405,305 CN9.33@3400,305 ; CN8.4@4700,600 4550,750 3470,750 3350,630 3350,405 3400,355 CN9.33@3400,305
LCD_RSTN: CN8.17 CN9.30 CN10.4 CN11.5 JP4.1 R59.2 R64.1 | length 3855.7
  Top Layer w12: R59.2@2890,755 2908,773 3242,773 3320,695 ; 3315,700 3320,695 ; CN8.17@3400,600 3400,615 3320,695
  Top Layer w20: JP4.1@2645,235 R64.1@2645,350
  Bottom Layer w12: CN11.5@1300,180 CN11.5@1300,200 1350,250 1500,250 ; CN10.4@1500,285 1500,250 ; CN10.4@1500,300 CN10.4@1520,300 ; CN8.17@3400,600 3450,550 3450,275 3425,250 3345,250 ; CN9.30@3600,200 3543,143 3376,143 3345,174 3345,250 ; 1500,250 1525,250 1550,225 1550,160 1595,115 2090,115 2245,270 3325,270 3345,250
LCD_SCK: CN10.7 CN11.3 R71.2 | length 855.9
  Top Layer w12: CN11.3@1098.78,188.85 1133.91,153.72 ; CN11.3@1098.82,198.82 CN11.3@1100,200 ; 1133.95,153.69 ccw(c1179.12,198.93) 1179.12,135 1395.25,135 ccw(c1395.25,194.75) 1437.47,152.47 ; 1437.5,152.5 ccw(c1407.32,182.68) 1450,182.68 1450,391.72 ; 1450,391.72 cw(c1518.28,391.72) R71.2@1470,440 ccw(c1518.28,391.72) 1450,391.72
  Bottom Layer w12: CN11.3@1100,200 CN10.7@1200,300
LCD_SDI: CN10.6 CN11.4 R65.2 | length 268
  Top Layer w12: CN11.4@1198.82,188.82 CN11.4@1200,190 ; CN10.6@1285.08,300 CN10.6@1300,300 ; CN10.6@1290,325 R65.2@1290,435
  Bottom Layer w12: CN11.4@1200,200 CN10.6@1300,300
LCD_SDO: CN10.9 CN11.8 R68.2 | length 1488.4
  Top Layer w12: R68.2@1350,440 1350,270 1330,250 1050,250 CN10.9@1000,300 ; CN11.8@1595,195 CN11.8@1600,190 ; CN11.8@1600,200 CN11.8@1600,190 ; CN10.9@1000,295 997.5,297.5 CN10.9@1000,300 ; CN10.9@1000,295 950,245 950,130 1010,70 1455,70 1575,190 CN11.8@1600,190 ; CN10.9@1000,295 CN10.9@1000,300
LCD_WR: CN8.5 CN9.32 R62.2 | length 2175.8
  Top Layer w12: R62.2@3442.5,697.5 3485,655 3525,655 3550,630 3550,250 CN9.32@3500,200
  Bottom Layer w12: CN9.32@3500,200 3525,200 3570,245 3620,245 3650,275 3650,365 3750,465 3750,640 3800,690 4425,690 4450,665 4450,575 4475,550 4550,550 CN8.5@4600,600
MG_DM: CJ3.2 R13.2 | length 1732.1
  Top Layer w12: R13.2@3429,1769 3429,1828 cw(c3527.98,1828) 3457.96,1897.96 ; 3457.99,1897.99 ccw(c3527.98,1828) 3457.96,1897.96 ; 3652.62,2092.62 ccw(c3584.1,2161.14) 3652.66,2092.66 ; CJ3.2@3681,3405 3681,2161.14 cw(c3584.1,2161.14) 3652.66,2092.66 ; 3457.96,1897.96 3652.66,2092.66
MG_DP: CJ3.3 R12.2 | length 1730.7
  Top Layer w12: 3411,1769 3411,1834 ; 3411,1835.03 cw(c3511,1835.03) 3440.29,1905.75 3633.71,2099.17 ccw(c3563,2169.88) 3663,2169.88 CJ3.3@3663,3405
MG_PA0: R55.2 R100.2 U1.74 | length 1077.8
  Top Layer w9: v2(3005,1895) 3019.45,1895 3064.88,1940.43 U1.74@3064.88,1656.22
  Bottom Layer w12: R55.2@2860,2500 2875,2485 2875,1940 2920,1895 v2(3005,1895)
MG_PA1: R56.2 R101.2 U1.75 | length 1105
  Top Layer w9: v2(2975,1925) 2975,1935 R101.2@2985,1945 ; R101.2@2995,1943.54 2980.73,1929.27 2980.73,1925 2975,1919.27 2975,1875 3049.13,1800.87 U1.75@3049.13,1656.22
  Bottom Layer w12: R56.2@2860,2600 2905,2555 2905,1947.54 2932.54,1920 2970,1920 v2(2975,1925)
MG_PA2: R57.2 R102.2 U1.76 | length 1130
  Top Layer w9: R102.2@2935,1945 v2@2947.6,1945 ; v2(2947.6,1950) v2@2947.6,1945 ; v2@2949.45,1945 v2@2947.6,1945 ; U1.76@3033.39,1656.22 3033.39,1786.61 2947.6,1872.4 v2@2947.6,1945
  Bottom Layer w12: R57.2@2860,2700 2934.92,2625.08 2934.92,1962.68 v2(2947.6,1950)
MG_PA3: R58.2 U1.77 | length 1361
  Top Layer w9: v2(2922.72,1867.28) 3017.64,1772.36 U1.77@3017.64,1656.22
  Bottom Layer w12: R58.2@2860,2800 2860,2765 2965,2660 2965,1990 3035,1920 3035,1880 3020,1865 2925,1865 v2@2923.64,1866.36
MG_PA4: R65.1 U1.78 | length 3011.7
  Top Layer w9: R65.1@1280,500 1315,535 1315,1425 1765,1875 2290,1875 2365,1950 2435,1950 2510,1875 2862,1875 3001.89,1735.11 U1.78@3001.89,1656.22
MG_PA5: R68.1 U1.79 | length 2848.2
  Top Layer w9: R68.1@1350,510 1350,1430 1770,1850 2857,1850 2986.14,1720.86 U1.79@2986.14,1656.22
MG_PA6: R71.1 U1.80 | length 2569.3
  Top Layer w12: R71.1@1480,507 1480,1433.58 cw(c1580,1433.58) 1509.29,1504.29 1710.71,1705.71 cw(c1781.42,1635) 1781.42,1735 2803.58,1735 cw(c2803.58,1635) 2874.29,1705.71 2875.71,1704.29 ccw(c2946.42,1775) 2946.42,1675 U1.80@2965.91,1675
MG_PA7: R72.1 U1.1 | length 2352.5
  Top Layer w9: R72.1@1575,500 1575,1440 1690,1555 2076.81,1555 2151.81,1630 2799,1630 2859.39,1569.61 U1.1@2883.78,1569.61
MG_PA8: R41.2 U1.2 | length 1195.1
  Top Layer w9: v2(2500,1600) 2799,1600 2845.14,1553.86 U1.2@2883.78,1553.86
  Bottom Layer w12: R41.2@2240,2200 2240,2190 2280,2150 2425,2150 2499,2076 v2@2499,1600
MG_PA9: R40.2 U1.3 | length 1136.7
  Top Layer w9: v2(2460,1600) 2485,1575 2794,1575 2830.89,1538.11 U1.3@2883.78,1538.11
  Bottom Layer w12: R40.2@2240,2100 R40.2@2240,2090 2240,2083 2273,2050 2430,2050 2465,2015 2465,1605 v2(2460,1600)
MG_PA10: R30.1 R43.2 R130.2 U1.4 | length 2014.1
  Top Layer w9: 2805.11,1527.38 ccw(c2825,1564.28) 2825,1522.36 U1.4@2883.78,1522.36
  Top Layer w12: R30.1@2035,2287 v2@2060,2312 ; v2@2150,1590 2359.64,1590 cw(c2359.64,1504.64) 2420,1565 ccw(c2468.28,1613.28) 2468.28,1545 2760,1545 cw(c2760,1478.44) 2794.86,1535.14 cw(c2760,1478.44) 2805.11,1527.38
  Bottom Layer w12: R130.2@2215.21,1460.21 2215.21,1482.79 ccw(c2115.21,1482.79) 2185.92,1553.51 v2(2150.71,1588.71) 2069.29,1670.13 cw(c2140,1740.84) 2040,1740.42 2040,2342.58 cw(c2140,2342.58) 2069.29,2413.29 2115.71,2459.71 cw(c2186.42,2389) 2186.42,2489 R43.2@2245,2489
  other v2: 2056,2315
MG_PA11: R42.2 R131.2 U1.5 | length 1654.4
  Top Layer w9: v2(2250,1560) 2355,1560 2400,1515 v2(2620,1515) 2650,1515 2658.39,1506.61 U1.5@2883.78,1506.61
  Bottom Layer w12: R42.2@2240,2400 2240,2395 2120,2275 2120,1720 2250,1590 v2(2250,1560) ; R131.2@2620,1460 v2(2620,1515)
MG_PA12: R39.2 R117.2 U1.6 | length 3534
  Top Layer w9: v2(1610,635) 1598.78,646.22 1598.78,1430.15 1698.62,1530 2305,1530 2310,1535 2345,1535 2395,1485 2814.13,1485 2820,1490.87 U1.6@2883.78,1490.87
  Bottom Layer w12: R117.2@820,650 870,600 1565,600 1605,640 v2(1610,635) ; R39.2@2240,2000 2172,1932 2172,1748.4 2305,1615.4 v2(2305,1532) v2@2305,1530
MG_PA13: R38.2 R120.2 U1.7 | length 3216.1
  Top Layer w9: v2(1623.78,670) 1623.78,1419.8 1708.98,1505 v2(2335,1505) 2340,1505 2385,1460 2825,1460 2840.12,1475.12 U1.7@2883.78,1475.12
  Bottom Layer w12: R120.2@970,650 990,630 1555,630 1595,670 v2(1623.78,670) ; R38.2@2240,1900 2200,1860 2200,1760 2335,1625 v2(2335,1505)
